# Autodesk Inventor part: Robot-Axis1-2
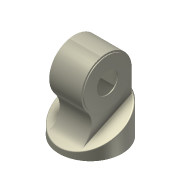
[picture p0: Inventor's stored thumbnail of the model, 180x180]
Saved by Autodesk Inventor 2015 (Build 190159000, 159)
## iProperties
Shininess: 21.0
Length Units: 11269
Angle Units: 11279
Time Units: 11290
Mass Units: 11283
Length Display Precision: 3
Angle Display Precision: 2
Created: 2001-08
Part Number: Robot-Axis1-2
Document SubType Name: ﾓﾃﾞﾘﾝｸﾞ
Designer: Administrator
Density: 1 g/cm^3
Material: Generic
Appearance: Smooth - Ivory
Density: 0.0
Volumn: 0.0
Area: 0.0
PropertySet Name: Model Information
Control State: 0
Master: False
Checked Out: False
Author: Administrator
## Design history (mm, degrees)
node "Center-Work Plane"
fillet "Chamfer" dims "d19" = 2
node "Sketch6"
sketch "Sketch7"
  geometry: C1 r 56 at (-128, 0); A1 r 60 centre (-128, 0) between (-128, 60) and (-89.273, -45.828) reference
  constraints: 1 centre point, 1 coincident
  dimensions: "d20" = 4 radial gap between concentric circles of A1 C1
extrude "Extrusion6" join sketch "Sketch7" distance "d21" = 2; taper "d22" = 0 deg
mirror "Mirror3"
shell "Shell1" dims "d25" = 2
sketch "Sketch10"
  geometry: C1 r 75 at (0, 0) reference
hole "Hole1" sketch "Sketch10" at (0, 0) diameter "d26" = 50; stored, may be unused: countersink angle "d30" = 82 deg, drill point angle "d32" = 118 deg; dims "d27" = 6, "d28" = 4, "d29" = 2, "d31" = 2
sketch "Sketch11"
  geometry: C1 r 56 at (0, 0) reference
hole "Hole2" sketch "Sketch11" at (0, 0) diameter "d33" = 50; stored, may be unused: countersink angle "d37" = 82 deg, drill point angle "d39" = 118 deg; dims "d34" = 6, "d35" = 4, "d36" = 2, "d38" = 2
body "Solid1"
sketch "ｽｹｯﾁ1"
  geometry: C1 r 75 at (0, 0)
  constraints: 1 centre point
  dimensions: "d0" = 150 diameter of C1
extrude "Extrusion1" new body sketch "ｽｹｯﾁ1" distance "d1" = 120; taper "d2" = 0 deg
sketch "ｽｹｯﾁ3"
  geometry: L1 (-75, 0)-(-75, 120) reference; L2 (75, 0)-(75, 120) reference; L3 (-75, 0)-(75, 0) reference; L4 (-75, 13)-(75, 82.946)
  constraints: 2 end point, 2 point on line
  dimensions: "d7" = 13 distance from line of L3 L4.start; "d8" = 25 deg angle of L3 L4
extrude "Extrusion3" sketch "ｽｹｯﾁ3" stored distance "d9" = 155; taper "d10" = 0 deg
sketch "Sketch4"
  geometry: L1 (0, 0)-(0, 128); L2 (-60, 128)-(60, 128); L3 (75, 82.946)-(-75, 13) reference; L4 (-75, 0)-(75, 0) reference; L5 (60, 128)-(60, 75.952); L6 (-61.181, 19.444)-(60, 75.952); A1 r 60 centre (0, 128) between (-60, 128) and (60, 128); A2 r 45 centre (-80.199, 60.228) between (-61.181, 19.444) and (-45.828, 89.273); 1 further point
  constraints: 8 end point, 5 point on circle, 4 tangent, 3 point on line, 2 centre point, 2 perpendicular, 1 coincident, 1 midpoint, 1 vertical, 1 other
  dimensions: "d11" = 120 diameter of A1; "d12" = 90 diameter of A2; "d13" = 128 distance between parallel lines of L4 L2
extrude "Extrusion4" join sketch "Sketch4" stored distance "d14" = 76; taper "d15" = 0 deg
